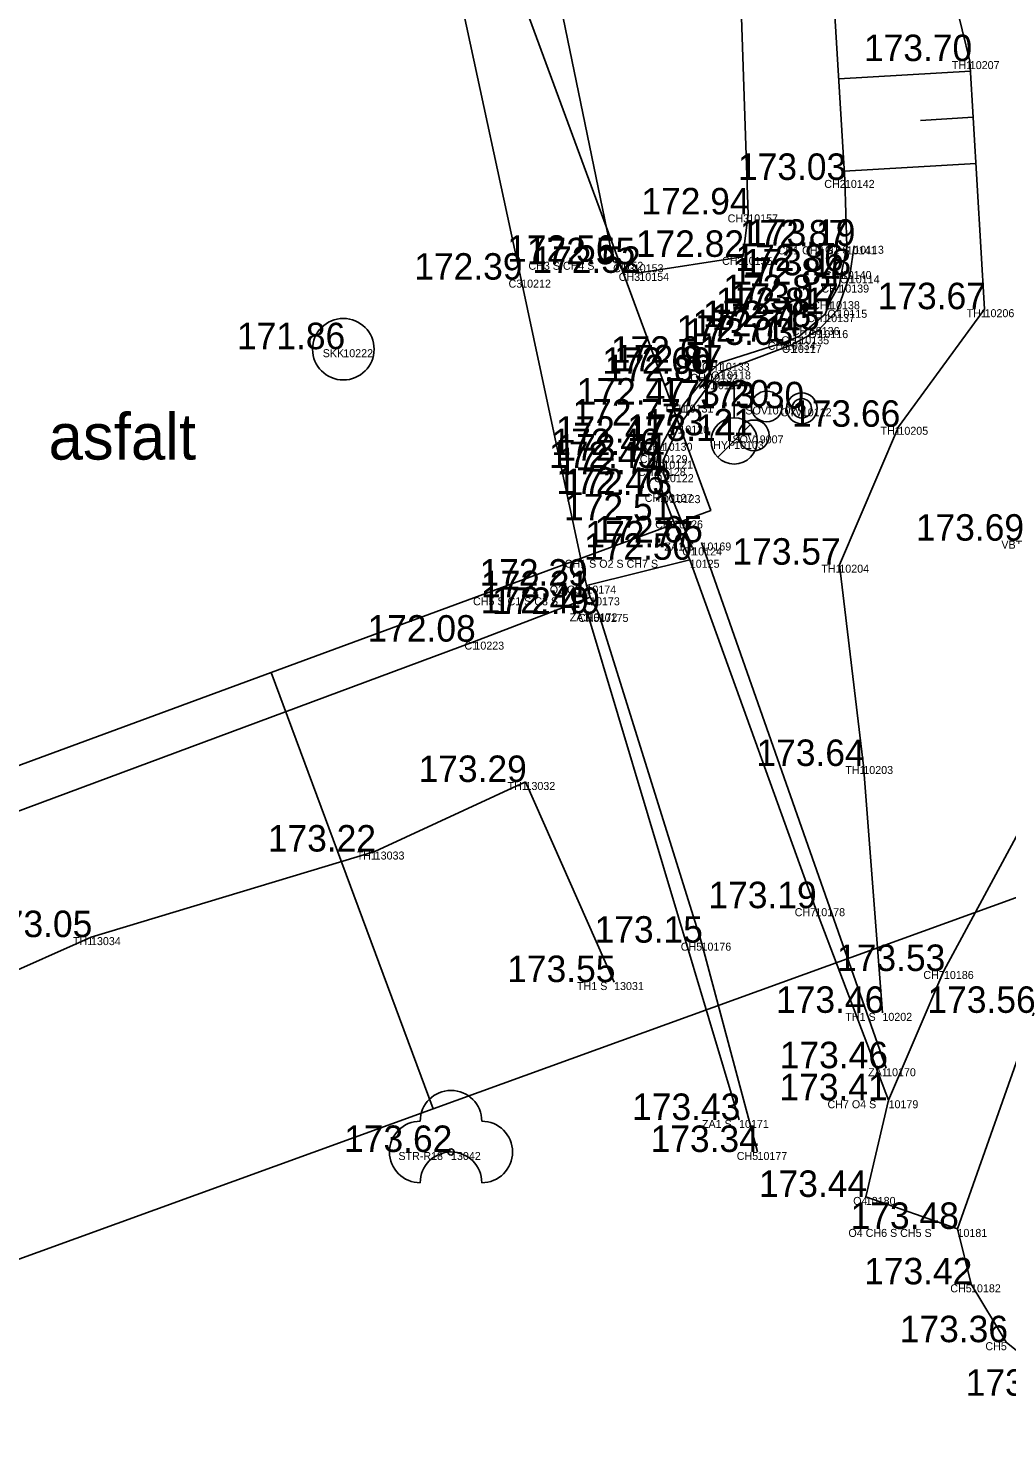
# Model space of a CAD drawing. Extents: x -566117 to -565580, y -1202428 to -1201938.
# Drawn here: x -565717.74 to -565701.84, y -1202302.21 to -1202279.21 of the extents above; entities that cross this region are included whole.
import ezdxf

# ---------------------------------------------------------------- set-up
doc = ezdxf.new("R2010")
doc.units = 0
for name, color, linetype in [('(Construction', 7, 'Continuous'), ('_0', 7, 'Continuous'), ('Bod', 7, 'Continuous'), ('CIZÍ_NADZEM', 7, 'Continuous'), ('Implicitní', 7, 'Continuous'), ('Kanalizace', 7, 'Continuous'), ('Katastr', 7, 'Continuous'), ('Kod', 7, 'Continuous'), ('POMOC_POPIS', 7, 'Continuous'), ('Voda', 7, 'Continuous'), ('Výška', 7, 'Continuous'), ('ZELEŇ', 7, 'Continuous'), ('Zpevněné plohy', 7, 'Continuous'), ('Číslo', 7, 'Continuous')]:
    doc.layers.add(name, color=color, linetype=linetype)

# ---------------------------------------------------------------- blocks, each defined once
blk = doc.blocks.new('A$C69D74C1E')
at = {"layer": 'Katastr'}
for p, q in [((353.77, -228.32), (351.14, -221.23)), ((368.8, -222.87), (353.77, -228.32)), ((311.62, -243.6), (353.77, -228.32))]:
    blk.add_line(p, q, dxfattribs=at)
for points in [[(351.14, -221.23), (358.28, -218.6), (344.09, -180.12), (336.92, -182.75)], [(351.14, -221.23), (319.78, -232.78), (322.2, -239.35), (268.21, -259.24), (266.13, -253.61), (252.38, -258.68)]]:
    blk.add_lwpolyline(points, dxfattribs=at)
blk = doc.blocks.new('SV')
at = {"layer": 'Voda'}
blk.add_circle((0, 0), 0.25, dxfattribs=at)
blk = doc.blocks.new('OS')
at = {"layer": 'Voda'}
for radius in [0.25, 0.158, 0.05]:
    blk.add_circle((0, 0), radius, dxfattribs=at)
blk = doc.blocks.new('STROM')
at = {"layer": 'ZELEŇ'}
blk.add_circle((0, 0), 0.05, dxfattribs=at)
for centre, start, end in [((0, 0.5), 0, 180), ((-0.5, 0), 90, 270), ((0.5, 0), 270, 90), ((0, -0.5), 0, 180)]:
    blk.add_arc(centre, 0.5, start, end, dxfattribs=at)
blk = doc.blocks.new('SAK')
at = {"layer": 'Kanalizace'}
blk.add_circle((0, 0), 0.5, dxfattribs=at)
blk = doc.blocks.new('HYP')
at = {"layer": 'CIZÍ_NADZEM'}
for p, q in [((-0.25, 0.899), (0.25, 0.899)), ((0, 0.375), (0, 0.899)), ((-0.265, -0.265), (0.265, 0.265))]:
    blk.add_line(p, q, dxfattribs=at)
blk.add_circle((0, 0), 0.375, dxfattribs=at)
blk = doc.blocks.new('POINT_DISPLAY')
at = {"layer": 'Implicitní'}
blk.add_line((0, 0), (0, 0), dxfattribs=at)

msp = doc.modelspace()

# ---------------------------------------------------------------- linework, layer by layer
at = {"layer": '(Construction'}
for p, q in [((-565702.43, -1202279.903), (-565704.57, -1202280.03)), ((-565702.386, -1202280.652), (-565703.241, -1202280.703)), ((-565702.341, -1202281.401), (-565704.479, -1202281.528))]:
    msp.add_line(p, q, dxfattribs=at)
at = {"layer": '_0'}
for p, q in [((-565706.8, -1202287.56), (-565703.8, -1202296.1)), ((-565706.19, -1202296.94), (-565708.65, -1202288.71))]:
    msp.add_line(p, q, dxfattribs=at)
at = {"layer": 'Zpevněné plohy'}
for p, q in [((-565709.73, -1202283.29), (-565711.15, -1202276.72)), ((-565708.23, -1202283), (-565709.34, -1202277.61)), ((-565706.04, -1202282.23), (-565706.15, -1202279.03)), ((-565702.2, -1202283.77), (-565702.44, -1202279.74)), ((-565706.13, -1202282.92), (-565706.04, -1202282.23)), ((-565704.52, -1202283.15), (-565704.44, -1202282.75)), ((-565704.32, -1202282.74), (-565704.39, -1202283.22)), ((-565708.23, -1202283), (-565707.9, -1202283.04)), ((-565707.9, -1202283.04), (-565707.81, -1202283.18)), ((-565707.81, -1202283.18), (-565706.13, -1202282.92)), ((-565708.67, -1202288.26), (-565709.73, -1202283.29)), ((-565704.39, -1202283.22), (-565704.59, -1202283.78)), ((-565704.56, -1202283.37), (-565704.52, -1202283.15)), ((-565704.71, -1202283.64), (-565704.56, -1202283.37)), ((-565704.59, -1202283.78), (-565704.9, -1202284.11)), ((-565704.79, -1202283.85), (-565704.71, -1202283.64)), ((-565703.6, -1202285.68), (-565702.2, -1202283.77)), ((-565705.04, -1202284.06), (-565704.79, -1202283.85)), ((-565705.43, -1202284.3), (-565705.21, -1202284.21)), ((-565704.9, -1202284.11), (-565705.33, -1202284.35)), ((-565705.21, -1202284.21), (-565705.04, -1202284.06)), ((-565706.5, -1202284.64), (-565705.43, -1202284.3)), ((-565705.33, -1202284.35), (-565706.48, -1202284.78)), ((-565706.69, -1202284.82), (-565706.5, -1202284.64)), ((-565706.63, -1202284.94), (-565707.16, -1202285.66)), ((-565707.09, -1202285.32), (-565706.69, -1202284.82)), ((-565706.48, -1202284.78), (-565706.63, -1202284.94)), ((-565707.43, -1202285.94), (-565707.09, -1202285.32)), ((-565707.16, -1202285.66), (-565707.42, -1202286.23)), ((-565704.56, -1202287.92), (-565703.6, -1202285.68)), ((-565707.51, -1202286.14), (-565707.43, -1202285.94)), ((-565707.54, -1202286.35), (-565707.51, -1202286.14)), ((-565707.42, -1202286.23), (-565707.41, -1202286.45)), ((-565707.43, -1202286.77), (-565707.54, -1202286.35)), ((-565707.41, -1202286.45), (-565707.3, -1202286.79)), ((-565707.26, -1202287.2), (-565707.43, -1202286.77)), ((-565707.3, -1202286.79), (-565706.95, -1202287.64)), ((-565706.99, -1202287.84), (-565707.26, -1202287.2)), ((-565706.99, -1202287.84), (-565708.67, -1202288.26)), ((-565706.99, -1202287.84), (-565704.95, -1202293.5)), ((-565704.17, -1202291.19), (-565704.56, -1202287.92)), ((-565708.61, -1202288.45), (-565708.67, -1202288.26)), ((-565708.61, -1202288.45), (-565710.49, -1202289.17)), ((-565708.61, -1202288.45), (-565708.47, -1202288.72)), ((-565708.47, -1202288.72), (-565706.8, -1202294.06)), ((-565703.86, -1202295.2), (-565704.17, -1202291.19)), ((-565709.66, -1202291.45), (-565712.11, -1202292.58)), ((-565708.22, -1202294.7), (-565709.66, -1202291.45)), ((-565712.11, -1202292.58), (-565716.72, -1202293.97)), ((-565704.95, -1202293.5), (-565703.76, -1202296.62)), ((-565716.72, -1202293.97), (-565719.71, -1202295.3)), ((-565706.8, -1202294.06), (-565705.89, -1202297.46)), ((-565702.64, -1202298.71), (-565701.4, -1202295.2)), ((-565703.76, -1202296.62), (-565704.13, -1202298.19)), ((-565704.13, -1202298.19), (-565702.64, -1202298.71)), ((-565702.64, -1202298.71), (-565702.42, -1202299.61)), ((-565702.42, -1202299.61), (-565701.85, -1202300.55)), ((-565701.85, -1202300.55), (-565700.77, -1202301.42))]:
    msp.add_line(p, q, dxfattribs=at)
for points in [[(-565702.44, -1202279.74), (-565703.06, -1202277.19), (-565704.48, -1202273.79)], [(-565704.44, -1202282.75), (-565704.47, -1202281.67), (-565704.73, -1202277.39)], [(-565703.76, -1202296.62), (-565702.86, -1202294.52), (-565699.56, -1202288.4), (-565698.44, -1202286.33)], [(-565710.49, -1202289.17), (-565721.72, -1202293.34), (-565733.77, -1202297.89)]]:
    msp.add_lwpolyline(points, dxfattribs=at)

# ---------------------------------------------------------------- block references
at = {"layer": 'Bod'}
for p in [(-565702.44, -1202279.74), (-565704.47, -1202281.67), (-565706.04, -1202282.23), (-565704.44, -1202282.75), (-565704.32, -1202282.74), (-565708.23, -1202283), (-565707.9, -1202283.04), (-565706.13, -1202282.92), (-565709.73, -1202283.29), (-565707.81, -1202283.18), (-565704.52, -1202283.15), (-565704.39, -1202283.22), (-565704.56, -1202283.37), (-565704.71, -1202283.64), (-565704.59, -1202283.78), (-565702.2, -1202283.77), (-565704.79, -1202283.85), (-565705.21, -1202284.21), (-565705.04, -1202284.06), (-565704.9, -1202284.11), (-565712.62, -1202284.42), (-565705.43, -1202284.3), (-565705.33, -1202284.35), (-565706.5, -1202284.64), (-565706.69, -1202284.82), (-565706.63, -1202284.94), (-565706.48, -1202284.78), (-565707.09, -1202285.32), (-565705.74, -1202285.35), (-565705.17, -1202285.38), (-565707.16, -1202285.66), (-565705.95, -1202285.82), (-565703.6, -1202285.68), (-565707.43, -1202285.94), (-565706.27, -1202285.91), (-565707.51, -1202286.14), (-565707.42, -1202286.23), (-565707.54, -1202286.35), (-565707.41, -1202286.45), (-565707.43, -1202286.77), (-565707.3, -1202286.79), (-565707.26, -1202287.2), (-565706.95, -1202287.64), (-565706.8, -1202287.56), (-565706.99, -1202287.84), (-565704.56, -1202287.92), (-565708.67, -1202288.26), (-565708.61, -1202288.45), (-565708.65, -1202288.71), (-565708.47, -1202288.72), (-565710.49, -1202289.17), (-565704.17, -1202291.19), (-565709.66, -1202291.45), (-565712.11, -1202292.58), (-565704.95, -1202293.5), (-565716.72, -1202293.97), (-565706.8, -1202294.06), (-565702.86, -1202294.52), (-565708.22, -1202294.7), (-565703.86, -1202295.2), (-565703.8, -1202296.1), (-565703.76, -1202296.62), (-565706.19, -1202296.94), (-565710.87, -1202297.46), (-565705.89, -1202297.46), (-565704.13, -1202298.19), (-565702.64, -1202298.71), (-565702.42, -1202299.61), (-565701.85, -1202300.55)]:
    msp.add_blockref('POINT_DISPLAY', p, dxfattribs=at)
at = {"layer": 'CIZÍ_NADZEM'}
msp.add_blockref('HYP', (-565706.27, -1202285.91), dxfattribs=at)
at = {"layer": 'Implicitní'}
msp.add_blockref('A$C69D74C1E', (-566064.93, -1202068.44), dxfattribs=at)
at = {"layer": 'Kanalizace'}
msp.add_blockref('SAK', (-565712.62, -1202284.42), dxfattribs=at)
at = {"layer": 'Voda'}
for name, p in [('SV', (-565705.74, -1202285.35)), ('OS', (-565705.17, -1202285.38)), ('SV', (-565705.95, -1202285.82))]:
    msp.add_blockref(name, p, dxfattribs=at)
at = {"layer": 'ZELEŇ'}
msp.add_blockref('STROM', (-565710.87, -1202297.46), dxfattribs=at)

# ---------------------------------------------------------------- texts
at = {"layer": 'Kod'}
for s, p in [('TH1', (-565702.732, -1202279.87)), ('CH2', (-565704.805, -1202281.8)), ('CH3', (-565706.375, -1202282.36)), ('CH1 CH2 S', (-565705.562, -1202282.88)), ('O1 S', (-565704.792, -1202282.87)), ('CH3 S CH4 S', (-565709.612, -1202283.13)), ('CH3', (-565708.235, -1202283.17)), ('CH3', (-565706.465, -1202283.05)), ('C3', (-565709.935, -1202283.42)), ('CH3', (-565708.145, -1202283.31)), ('CH1', (-565704.812, -1202283.28)), ('O1', (-565704.552, -1202283.35)), ('CH1', (-565704.852, -1202283.5)), ('CH1', (-565705.002, -1202283.77)), ('O1', (-565704.752, -1202283.91)), ('TH1', (-565702.492, -1202283.9)), ('CH1', (-565705.082, -1202283.98)), ('CH1', (-565705.502, -1202284.34)), ('CH1', (-565705.332, -1202284.19)), ('O1', (-565705.062, -1202284.24)), ('SKK', (-565712.955, -1202284.55)), ('CH1', (-565705.722, -1202284.43)), ('O1', (-565705.492, -1202284.48)), ('CH1', (-565706.792, -1202284.77)), ('CH1', (-565706.982, -1202284.95)), ('O1', (-565706.792, -1202285.07)), ('O1', (-565706.642, -1202284.91)), ('CH1', (-565707.382, -1202285.45)), ('SOV', (-565706.087, -1202285.48)), ('OTV', (-565705.517, -1202285.51)), ('O1', (-565707.322, -1202285.79)), ('SOV', (-565706.297, -1202285.95)), ('TH1', (-565703.892, -1202285.81)), ('CH1', (-565707.722, -1202286.07)), ('HYP', (-565706.611, -1202286.04)), ('CH1', (-565707.802, -1202286.27)), ('O1', (-565707.582, -1202286.36)), ('CH1', (-565707.832, -1202286.48)), ('O1', (-565707.572, -1202286.58)), ('CH1', (-565707.722, -1202286.9)), ('O1', (-565707.462, -1202286.92)), ('CH1', (-565707.552, -1202287.33)), ('ZA1 S', (-565707.402, -1202287.69)), ('O1', (-565707.112, -1202287.77)), ('VBT', (-565701.927, -1202287.66)), ('CH1 S O2 S CH7 S', (-565709.022, -1202287.97)), ('TH1', (-565704.852, -1202288.05)), ('O2 C3', (-565709.265, -1202288.39)), ('CH5 S C1 S C3 S', (-565710.512, -1202288.58)), ('ZA1', (-565708.942, -1202288.84)), ('CH5', (-565708.807, -1202288.85)), ('C1', (-565710.652, -1202289.3)), ('TH1', (-565704.462, -1202291.32)), ('TH1', (-565709.952, -1202291.58)), ('TH1', (-565712.402, -1202292.71)), ('CH7', (-565705.285, -1202293.63)), ('TH1', (-565717.012, -1202294.1)), ('CH5', (-565707.137, -1202294.19)), ('CH7', (-565703.195, -1202294.65)), ('TH1 S', (-565708.822, -1202294.83)), ('TH1 S', (-565704.462, -1202295.33)), ('ZA1', (-565704.092, -1202296.23)), ('CH7 O4 S', (-565704.752, -1202296.75)), ('ZA1 S', (-565706.792, -1202297.07)), ('STR-R18', (-565711.725, -1202297.59)), ('CH5', (-565706.227, -1202297.59)), ('O4', (-565704.335, -1202298.32)), ('O4 CH6 S CH5 S', (-565704.412, -1202298.84)), ('CH5', (-565702.757, -1202299.74)), ('CH5', (-565702.187, -1202300.68))]:
    msp.add_text(s, height=0.13, dxfattribs=at).set_placement(p)
at = {"layer": 'POMOC_POPIS'}
msp.add_text('asfalt', height=0.75, dxfattribs=at).set_placement((-565717.41, -1202286.213))
at = {"layer": 'Výška'}
for s, p in [('173.70 ', (-565704.16, -1202279.74)), ('173.03 ', (-565706.207, -1202281.67)), ('172.94 ', (-565707.777, -1202282.23)), ('172.87 ', (-565706.177, -1202282.75)), ('173.19 ', (-565706.057, -1202282.74)), ('172.56 ', (-565709.958, -1202283)), ('172.55 ', (-565709.637, -1202283.04)), ('172.82 ', (-565707.867, -1202282.92)), ('172.39 ', (-565711.467, -1202283.29)), ('172.52 ', (-565709.547, -1202283.18)), ('172.86 ', (-565706.248, -1202283.15)), ('173.18 ', (-565706.127, -1202283.22)), ('172.84 ', (-565706.297, -1202283.37)), ('172.82 ', (-565706.447, -1202283.64)), ('173.17 ', (-565706.327, -1202283.78)), ('173.67 ', (-565703.937, -1202283.77)), ('172.81 ', (-565706.563, -1202283.85)), ('172.74 ', (-565706.947, -1202284.21)), ('172.78 ', (-565706.777, -1202284.06)), ('173.15 ', (-565706.637, -1202284.11)), ('171.86 ', (-565714.348, -1202284.42)), ('172.71 ', (-565707.203, -1202284.3)), ('173.03 ', (-565707.067, -1202284.35)), ('172.61 ', (-565708.273, -1202284.64)), ('172.60 ', (-565708.41, -1202284.82)), ('172.89 ', (-565708.367, -1202284.94)), ('172.87 ', (-565708.217, -1202284.78)), ('172.47 ', (-565708.827, -1202285.32)), ('173.20 ', (-565707.46, -1202285.35)), ('173.30 ', (-565706.89, -1202285.38)), ('172.77 ', (-565708.897, -1202285.66)), ('173.21 ', (-565707.723, -1202285.82)), ('173.66 ', (-565705.328, -1202285.68)), ('172.47 ', (-565709.167, -1202285.94)), ('173.14 ', (-565708.007, -1202285.91)), ('172.46 ', (-565709.238, -1202286.14)), ('172.74 ', (-565709.157, -1202286.23)), ('172.45 ', (-565709.277, -1202286.35)), ('172.74 ', (-565709.147, -1202286.45)), ('172.46 ', (-565709.158, -1202286.77)), ('172.73 ', (-565709.037, -1202286.79)), ('172.51 ', (-565709.033, -1202287.2)), ('172.77 ', (-565708.687, -1202287.64)), ('172.65 ', (-565708.537, -1202287.56)), ('173.69 ', (-565703.317, -1202287.53)), ('172.50 ', (-565708.71, -1202287.84)), ('173.57 ', (-565706.297, -1202287.92)), ('172.29 ', (-565710.407, -1202288.26)), ('172.31 ', (-565710.383, -1202288.45)), ('172.49 ', (-565710.387, -1202288.71)), ('172.49 ', (-565710.207, -1202288.72)), ('172.08 ', (-565712.227, -1202289.17)), ('173.64 ', (-565705.907, -1202291.19)), ('173.29 ', (-565711.397, -1202291.45)), ('173.22 ', (-565713.847, -1202292.58)), ('173.19 ', (-565706.687, -1202293.5)), ('173.05 ', (-565718.457, -1202293.97)), ('173.15 ', (-565708.537, -1202294.06)), ('173.53 ', (-565704.597, -1202294.52)), ('173.55 ', (-565709.957, -1202294.7)), ('173.46 ', (-565705.588, -1202295.2)), ('173.56 ', (-565703.128, -1202295.2)), ('173.46 ', (-565705.528, -1202296.1)), ('173.41 ', (-565705.533, -1202296.62)), ('173.43 ', (-565707.927, -1202296.94)), ('173.62 ', (-565712.607, -1202297.46)), ('173.34 ', (-565707.627, -1202297.46)), ('173.44 ', (-565705.867, -1202298.19)), ('173.48 ', (-565704.377, -1202298.71)), ('173.42 ', (-565704.157, -1202299.61)), ('173.36 ', (-565703.578, -1202300.55)), ('173.22 ', (-565702.507, -1202301.42))]:
    msp.add_text(s, height=0.43, dxfattribs=at).set_placement(p)
at = {"layer": 'Číslo'}
for s, p in [('10207', (-565702.44, -1202279.87)), ('10142', (-565704.47, -1202281.8)), ('10157', (-565706.04, -1202282.36)), ('10141', (-565704.44, -1202282.88)), ('10113', (-565704.32, -1202282.87)), ('10152', (-565708.23, -1202283.13)), ('10153', (-565707.9, -1202283.17)), ('10155', (-565706.13, -1202283.05)), ('10212', (-565709.73, -1202283.42)), ('10154', (-565707.81, -1202283.31)), ('10140', (-565704.52, -1202283.28)), ('10114', (-565704.39, -1202283.35)), ('10139', (-565704.56, -1202283.5)), ('10138', (-565704.71, -1202283.77)), ('10115', (-565704.59, -1202283.91)), ('10206', (-565702.2, -1202283.9)), ('10137', (-565704.79, -1202283.98)), ('10135', (-565705.21, -1202284.34)), ('10136', (-565705.04, -1202284.19)), ('10116', (-565704.9, -1202284.24)), ('10222', (-565712.62, -1202284.55)), ('10134', (-565705.43, -1202284.43)), ('10117', (-565705.33, -1202284.48)), ('10133', (-565706.5, -1202284.77)), ('10132', (-565706.69, -1202284.95)), ('10119', (-565706.63, -1202285.07)), ('10118', (-565706.48, -1202284.91)), ('10131', (-565707.09, -1202285.45)), ('10102', (-565705.74, -1202285.48)), ('10112', (-565705.17, -1202285.51)), ('10120', (-565707.16, -1202285.79)), ('19007', (-565705.95, -1202285.95)), ('10205', (-565703.6, -1202285.81)), ('10130', (-565707.43, -1202286.07)), ('10103', (-565706.27, -1202286.04)), ('10129', (-565707.51, -1202286.27)), ('10121', (-565707.42, -1202286.36)), ('10128', (-565707.54, -1202286.48)), ('10122', (-565707.41, -1202286.58)), ('10127', (-565707.43, -1202286.9)), ('10123', (-565707.3, -1202286.92)), ('10126', (-565707.26, -1202287.33)), ('10124', (-565706.95, -1202287.77)), ('10169', (-565706.8, -1202287.69)), ('10125', (-565706.99, -1202287.97)), ('10204', (-565704.56, -1202288.05)), ('10174', (-565708.67, -1202288.39)), ('10173', (-565708.61, -1202288.58)), ('10172', (-565708.65, -1202288.84)), ('10175', (-565708.47, -1202288.85)), ('10223', (-565710.49, -1202289.3)), ('10203', (-565704.17, -1202291.32)), ('13032', (-565709.66, -1202291.58)), ('13033', (-565712.11, -1202292.71)), ('10178', (-565704.95, -1202293.63)), ('13034', (-565716.72, -1202294.1)), ('10176', (-565706.8, -1202294.19)), ('10186', (-565702.86, -1202294.65)), ('13031', (-565708.22, -1202294.83)), ('10202', (-565703.86, -1202295.33)), ('10170', (-565703.8, -1202296.23)), ('10179', (-565703.76, -1202296.75)), ('10171', (-565706.19, -1202297.07)), ('13042', (-565710.87, -1202297.59)), ('10177', (-565705.89, -1202297.59)), ('10180', (-565704.13, -1202298.32)), ('10181', (-565702.64, -1202298.84)), ('10182', (-565702.42, -1202299.74))]:
    msp.add_text(s, height=0.13, dxfattribs=at).set_placement(p)

doc.saveas('drawing.dxf')
